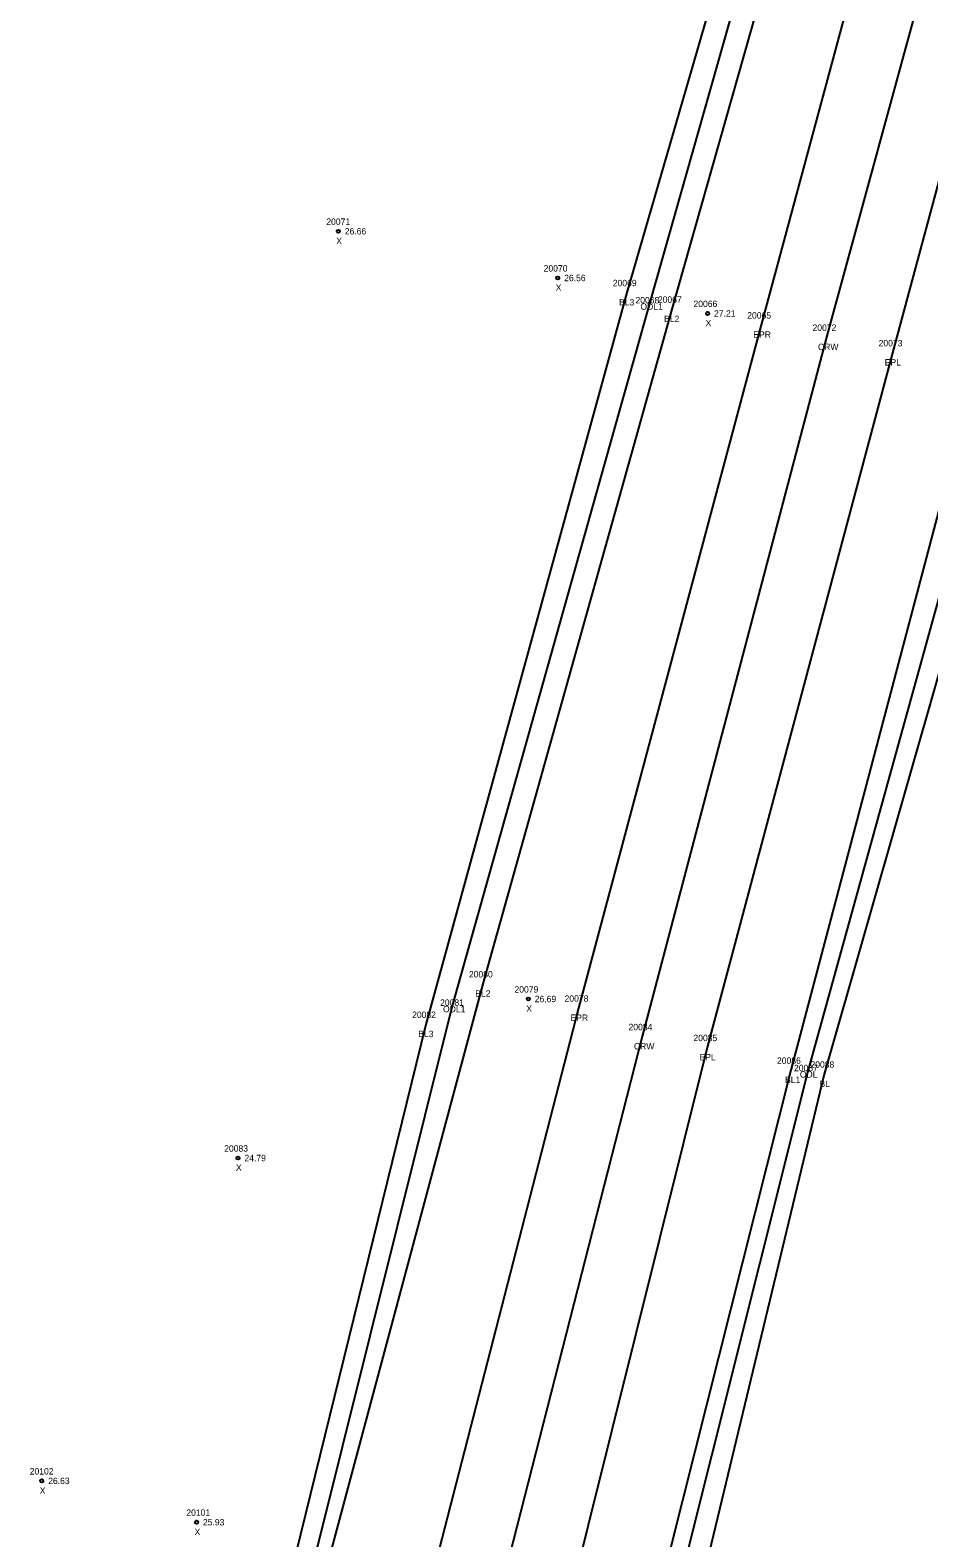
# Model space of a CAD drawing. Extents: x 2432729 to 2433340, y 684958 to 688103.
# Drawn here: x 2432880.7 to 2433020.9, y 687397.5 to 687632.9 of the extents above; entities that cross this region are included whole.
import ezdxf

# ---------------------------------------------------------------- set-up
doc = ezdxf.new("R2010")
doc.units = 0
for name, color, linetype in [('RD_DTM_BkLn1', 7, 'Continuous'), ('RD_EX_H2O', 7, 'Continuous'), ('RD_EX_H2O_txCode', 7, 'Continuous'), ('RD_EX_Road', 7, 'Continuous'), ('RD_EX_Road_txCode', 7, 'Continuous'), ('RD_Sketch8', 7, 'Continuous'), ('RD_SMD_Locator', 7, 'Continuous'), ('RD_SMD_Misc', 7, 'Continuous')]:
    doc.layers.add(name, color=color, linetype=linetype)

msp = doc.modelspace()

# ---------------------------------------------------------------- linework, layer by layer
at = {"layer": 'RD_DTM_BkLn1'}
for points in [[(2433118.26, 688093.2), (2433092.06, 687992.21), (2433063.59, 687892.57), (2433035.4, 687792.67), (2433003.26, 687693.63), (2432973.78, 687591.87), (2432942.45, 687477.63), (2432922.14, 687395), (2432910.39, 687336.67), (2432899.1, 687275.13), (2432892.65, 687218), (2432891.75, 687172.49)], [(2433125.46, 688091.48), (2433098.1, 687989.98), (2433070.67, 687890.07), (2433044.57, 687790.6), (2433009.89, 687691.98), (2432980.82, 687589.28), (2432951.34, 687483.95), (2432927.37, 687394.4), (2432914.6, 687336.1), (2432907.58, 687275.27), (2432904.68, 687217.27), (2432900.37, 687172.96), (2432891.75, 687172.49)], [(2433140.82, 688087.65), (2433112.94, 687984.39), (2433086.23, 687884.97), (2433060.15, 687787.81), (2433032.83, 687687.07), (2433004.93, 687584.9), (2432976.21, 687475.71), (2432953.67, 687387.58), (2432941.78, 687332.31), (2432932.37, 687274.14), (2432926.02, 687213.66), (2432924.35, 687158.94)], [(2433156.54, 688084.3), (2433128.42, 687980.72), (2433101.84, 687880.23), (2433076.15, 687783.58), (2433056.79, 687706.65), (2433053.61, 687680.85), (2433043.6, 687649.71), (2433027.96, 687578.58), (2432999.4, 687470.47), (2432976.82, 687380.76), (2432967.08, 687327.52), (2432956.82, 687270.44), (2432953.12, 687234.52), (2432952.13, 687211.69)], [(2433161.14, 688083.06), (2433133.45, 687979.3), (2433106.44, 687878.75), (2433080.34, 687782.58), (2433063.71, 687704.97), (2433062.78, 687678.91), (2433051.75, 687646.46), (2433035.42, 687577.73), (2433004.6, 687469.86), (2432982.67, 687378.73), (2432971.98, 687326.06), (2432962.83, 687268.71), (2432961.78, 687241.18), (2432987.4, 687248.62)]]:
    msp.add_lwpolyline(points, dxfattribs=at)
at = {"layer": 'RD_EX_H2O'}
for points in [[(2433122.48, 688092.22), (2433094.03, 687991.07), (2433066.93, 687892.02), (2433040.1, 687791.41), (2433006.23, 687692.29), (2432977.32, 687590.19), (2432946.52, 687480.52), (2432925.1, 687394.47), (2432912.11, 687336.21), (2432903.51, 687275.66), (2432898.99, 687217.48), (2432895.84, 687179.01)], [(2433158.82, 688083.82), (2433130.6, 687980.05), (2433103.89, 687879.65), (2433077.93, 687783.05), (2433058.91, 687706.24), (2433056.32, 687679.85), (2433046.3, 687648.55), (2433031.84, 687578.12), (2433002.04, 687470.32), (2432979.46, 687380.11), (2432969.67, 687326.76), (2432959.16, 687269.46), (2432956.03, 687234.5)]]:
    msp.add_lwpolyline(points, dxfattribs=at)
at = {"layer": 'RD_EX_Road'}
for points in [[(2433130.63, 688090.22), (2433103.18, 687988.73), (2433075.68, 687887.89), (2433049.83, 687790.75), (2433022.33, 687689.17), (2432994.76, 687586.82), (2432966.23, 687480.17), (2432943.15, 687390.42), (2432931.4, 687334.3), (2432921.83, 687273.88), (2432915.64, 687215.4), (2432913.86, 687159.12)], [(2433151.11, 688085.43), (2433123.35, 687982.08), (2433096.36, 687882.07), (2433070.62, 687785.25), (2433042.64, 687684.31), (2433015.24, 687582.49), (2432986.34, 687474.01), (2432964, 687384.38), (2432952.4, 687330.76), (2432943.09, 687273.42), (2432937.12, 687213.43), (2432935.51, 687158.7)]]:
    msp.add_lwpolyline(points, dxfattribs=at)
at = {"layer": 'RD_SMD_Locator'}
for centre, radius in [((2432928.78, 687601.45), 0.25), ((2432963.01, 687594.16), 0.25), ((2432973.78, 687591.87), 0.001), ((2432977.32, 687590.19), 0.001), ((2432980.82, 687589.28), 0.001), ((2432986.4, 687588.62), 0.25), ((2432994.76, 687586.82), 0.001), ((2433004.93, 687584.9), 0.001), ((2433015.24, 687582.49), 0.001), ((2432951.34, 687483.95), 0.001), ((2432946.52, 687480.52), 0.001), ((2432958.42, 687481.59), 0.25), ((2432966.23, 687480.17), 0.001), ((2432942.45, 687477.63), 0.001), ((2432976.21, 687475.71), 0.001), ((2432986.34, 687474.01), 0.001), ((2432999.4, 687470.47), 0.001), ((2433002.04, 687470.32), 0.001), ((2433004.6, 687469.86), 0.001), ((2432913.12, 687456.76), 0.25), ((2432882.5, 687406.35), 0.25), ((2432906.65, 687399.9), 0.25)]:
    msp.add_circle(centre, radius, dxfattribs=at)

# ---------------------------------------------------------------- texts
at = {"layer": 'RD_EX_H2O_txCode'}
for s, p in [('20068', (2432975.14, 687590.19)), ('ODL1', (2432975.91, 687589.19)), ('20081', (2432944.65, 687480.52)), ('ODL1', (2432945.11, 687479.52)), ('20087', (2432999.88, 687470.32)), ('ODL', (2433000.79, 687469.32))]:
    msp.add_text(s, height=1, dxfattribs=at).set_placement(p)
at = {"layer": 'RD_EX_Road_txCode'}
for s, p in [('20065', (2432992.58, 687587.82)), ('EPR', (2432993.53, 687584.82)), ('20073', (2433013.08, 687583.49)), ('EPL', (2433014.03, 687580.49)), ('20078', (2432964.08, 687481.17)), ('EPR', (2432965, 687478.17)), ('20085', (2432984.18, 687475.01)), ('EPL', (2432985.14, 687472.01))]:
    msp.add_text(s, height=1, dxfattribs=at).set_placement(p)
at = {"layer": 'RD_Sketch8'}
for s, p in [('20071', (2432926.9, 687602.45)), ('X', (2432928.46, 687599.45)), ('26.66', (2432929.78, 687600.95)), ('20070', (2432960.81, 687595.16)), ('X', (2432962.69, 687592.16)), ('26.56', (2432964.01, 687593.66)), ('20066', (2432984.19, 687589.62)), ('27.21', (2432987.4, 687588.12)), ('X', (2432986.08, 687586.62)), ('20079', (2432956.26, 687482.59)), ('X', (2432958.1, 687479.59)), ('26.69', (2432959.42, 687481.09)), ('20083', (2432910.96, 687457.76)), ('24.79', (2432914.12, 687456.26)), ('X', (2432912.8, 687454.76)), ('20102', (2432880.62, 687407.35)), ('X', (2432882.18, 687404.35)), ('26.63', (2432883.5, 687405.85)), ('20101', (2432905.06, 687400.9)), ('25.93', (2432907.65, 687399.4)), ('X', (2432906.34, 687397.9))]:
    msp.add_text(s, height=1, dxfattribs=at).set_placement(p)
at = {"layer": 'RD_SMD_Misc'}
for s, p in [('20069', (2432971.6, 687592.87)), ('BL3', (2432972.57, 687589.87)), ('20067', (2432978.64, 687590.28)), ('BL2', (2432979.61, 687587.28)), ('20072', (2433002.77, 687585.9)), ('CRW', (2433003.62, 687582.9)), ('20080', (2432949.15, 687484.95)), ('BL2', (2432950.14, 687481.95)), ('20082', (2432940.29, 687478.63)), ('20084', (2432974.06, 687476.71)), ('BL3', (2432941.24, 687475.63)), ('CRW', (2432974.9, 687473.71)), ('20086', (2432997.22, 687471.47)), ('20088', (2433002.44, 687470.86)), ('BL1', (2432998.48, 687468.47)), ('BL', (2433003.85, 687467.86))]:
    msp.add_text(s, height=1, dxfattribs=at).set_placement(p)

doc.saveas('drawing.dxf')
